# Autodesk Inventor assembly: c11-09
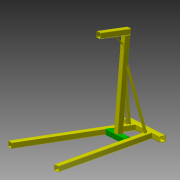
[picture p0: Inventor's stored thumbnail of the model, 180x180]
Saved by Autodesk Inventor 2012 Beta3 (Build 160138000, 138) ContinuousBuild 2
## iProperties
Created: 2011-01
Part Number: c11-09
Document SubType Name: Assembly
Designer: Beta-8540w
_SolveAssemblyDoc: Frame Generator Solve Assembly
_Version: 15.0.0
Author: Beta-8540w
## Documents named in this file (3)
- C:\Inventor 2012 Essentials\Assemblies\Chapter 11\c11-09.iam
- C:\Inventor 2012 Essentials\Parts\Chapter 11\c11-01.ipt
- C:\Inventor 2012 Essentials\Assemblies\Chapter 11\Frame\Frame c11-09.iam
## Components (2 placed, 2 different names)
1. c11-01:1
2. Frame c11-09:1 [sub-assembly]
